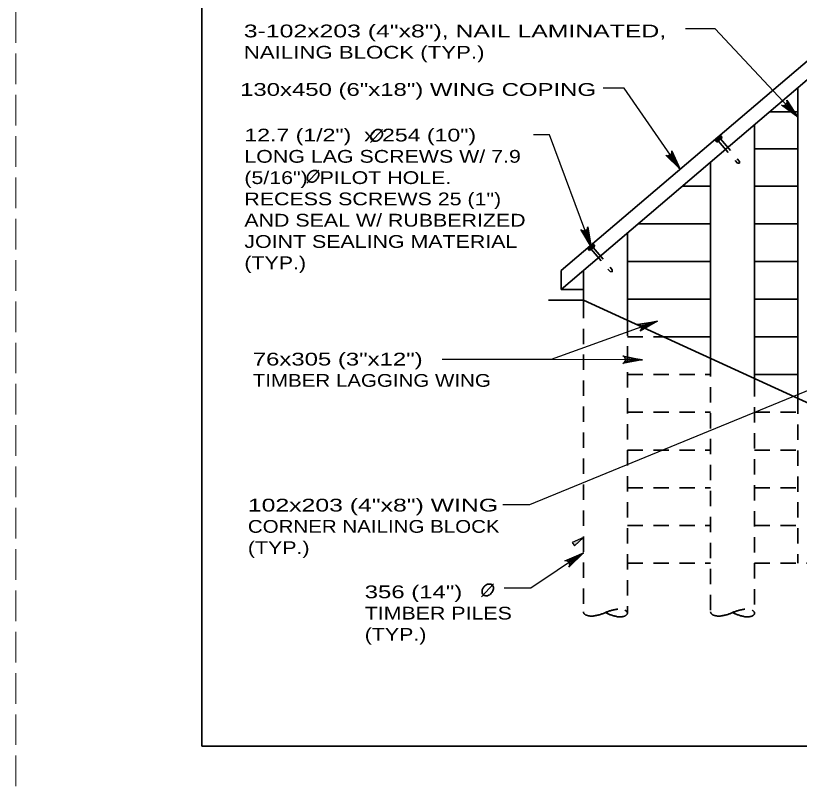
# Model space of a CAD drawing. Extents: x -6.4 to 73.1, y -66 to 0.
# Drawn here: x 0 to 7.36, y -43.62 to -36.39 of the extents above; entities that cross this region are included whole.
import ezdxf

# ---------------------------------------------------------------- set-up
doc = ezdxf.new("R2010")
doc.units = 0
doc.header["$LTSCALE"] = 0.048
doc.header["$PDMODE"] = 32
doc.header["$PDSIZE"] = 0.024
doc.linetypes.add('LONG_DASHED', pattern=[7.5, 6, -1.5])
doc.linetypes.add('MEDIUM_DASHED', pattern=[4.5, 3, -1.5])
for name, color, linetype, lineweight in [('1', 7, 'Continuous', 13), ('4', 7, 'Continuous', 25), ('5', 7, 'Continuous', 25), ('63', 7, 'LONG_DASHED', 13)]:
    doc.layers.add(name, color=color, linetype=linetype, lineweight=lineweight)

msp = doc.modelspace()

# ---------------------------------------------------------------- hatches: boundary and pattern name
at = {"layer": '5'}
for points in [[(7.34583, -37.3415), (7.2725, -37.24842), (7.25808, -37.26183)], [(5.22792, -41.33758), (5.249, -41.36892), (5.3325, -41.28992)], [(5.22792, -41.48342), (5.249, -41.51475), (5.3325, -41.43575)]]:
    msp.add_hatch(color=256, dxfattribs=at).paths.add_polyline_path(points)

# ---------------------------------------------------------------- linework, layer by layer
at = {"layer": '1', "lineweight": 35}
msp.add_lwpolyline([(1.75, -43.25), (33.25, -43.25), (33.25, -22.75), (1.75, -22.75)], close=True, dxfattribs=at)
at = {"layer": '4', "lineweight": 35}
for p, q in [((7.57942, -36.68917), (5.12433, -38.78225)), ((7.57942, -36.86633), (5.12433, -38.95942)), ((7.34583, -37.0655), (7.34583, -39.98392)), ((7.08275, -37.28975), (7.34583, -37.28975)), ((6.94125, -37.41042), (6.94125, -39.82258)), ((6.63567, -37.53292), (6.58458, -37.57642)), ((6.61208, -37.532), (6.5875, -37.553)), ((6.6105, -37.53833), (6.61842, -37.54767)), ((6.63567, -37.53292), (6.61633, -37.51025)), ((6.62625, -37.541), (6.61833, -37.53167)), ((6.58458, -37.57642), (6.56525, -37.55375)), ((6.59375, -37.56867), (6.58583, -37.55933)), ((6.59375, -37.56867), (6.62625, -37.541)), ((6.59425, -37.55217), (6.60217, -37.5615)), ((6.94125, -37.63908), (7.34583, -37.63908)), ((6.79825, -37.7745), (6.79917, -37.7565)), ((6.52783, -37.76283), (6.52783, -39.63292)), ((6.26333, -37.98833), (6.52783, -37.98833)), ((6.94125, -37.98833), (7.34583, -37.98833)), ((5.84775, -38.34267), (6.52783, -38.34267)), ((6.94125, -38.34267), (7.34583, -38.34267)), ((5.74592, -38.4295), (5.74592, -39.25017)), ((5.44033, -38.552), (5.38925, -38.5955)), ((5.41675, -38.55108), (5.39217, -38.57208)), ((5.39842, -38.58775), (5.43092, -38.56008)), ((5.39892, -38.57125), (5.40683, -38.58058)), ((5.41517, -38.55742), (5.42308, -38.56675)), ((5.44033, -38.552), (5.421, -38.52933)), ((5.43092, -38.56008), (5.423, -38.55075)), ((5.38925, -38.5955), (5.37, -38.57292)), ((5.39842, -38.58775), (5.3905, -38.57842)), ((5.74592, -38.697), (6.52783, -38.697)), ((6.94125, -38.697), (7.34583, -38.697)), ((5.12433, -38.78225), (5.12433, -38.95942)), ((5.3325, -38.78192), (5.3325, -39.08742)), ((5.12433, -38.95942), (5.3325, -38.95942)), ((5.00517, -39.06108), (5.3325, -39.06108)), ((5.33375, -39.06108), (7.8505, -40.21542)), ((5.74592, -39.05133), (6.52783, -39.05133)), ((6.94125, -39.05133), (7.34583, -39.05133)), ((6.085, -39.40567), (6.52783, -39.40567)), ((6.94125, -39.40567), (7.34583, -39.40567)), ((6.94125, -39.76), (7.34583, -39.76))]:
    msp.add_line(p, q, dxfattribs=at)
at = {"layer": '4', "linetype": 'MEDIUM_DASHED', "lineweight": 35}
for p, q in [((6.62, -37.54625), (6.79917, -37.7565)), ((5.42467, -38.56533), (5.60392, -38.77558)), ((5.3325, -39.08467), (5.3325, -41.99042)), ((5.74592, -39.25017), (5.74592, -42.0015)), ((5.74592, -39.29367), (5.74592, -39.36292)), ((5.74592, -39.40567), (6.085, -39.40567)), ((6.52783, -39.63292), (6.52783, -41.99042)), ((5.74592, -39.76), (6.52783, -39.76)), ((6.94125, -39.82258), (6.94125, -42.0015)), ((7.34583, -39.98392), (7.34583, -41.53167)), ((5.74592, -40.11433), (6.52783, -40.11433)), ((6.94125, -40.11433), (7.34583, -40.11433)), ((5.74592, -40.46867), (6.52783, -40.46867)), ((6.94125, -40.46867), (7.34583, -40.46867)), ((5.74592, -40.823), (6.52783, -40.823)), ((6.94125, -40.823), (7.34583, -40.823)), ((5.74592, -41.17733), (6.52783, -41.17733)), ((6.94125, -41.17733), (7.34583, -41.17733)), ((5.74592, -41.53167), (6.52783, -41.53167)), ((6.94125, -41.53167), (7.72817, -41.53167))]:
    msp.add_line(p, q, dxfattribs=at)
for points in [[(6.6, -37.56333), (6.77925, -37.7735), (6.79825, -37.7745)], [(5.40467, -38.58242), (5.58392, -38.79258), (5.603, -38.79358), (5.60392, -38.77558)]]:
    msp.add_lwpolyline(points, dxfattribs=at)
at = {"layer": '4', "lineweight": 35}
for centre, radius, start, end in [((6.61095, -37.5553), 0.01696, 91.4996, 169.39961), ((6.61546, -37.53624), 0.00539, 57.90141, 202.9978), ((6.59147, -37.5574), 0.00592, 128.62254, 199.16266), ((6.59147, -37.5574), 0.00592, 61.73655, 128.62254), ((5.39614, -38.57649), 0.00592, 61.73655, 128.62254), ((5.41562, -38.57439), 0.01696, 91.4996, 169.39961), ((5.42014, -38.55533), 0.00539, 57.90141, 202.9978), ((5.39614, -38.57649), 0.00592, 128.62254, 199.16266)]:
    msp.add_arc(centre, radius, start, end, dxfattribs=at)
at = {"layer": '4', "linetype": 'MEDIUM_DASHED', "lineweight": 35}
for centre, major_axis, start_param, end_param in [((5.40576, -41.99238), (-0.07323, 0.00196), 6.2831853, 8.1107827), ((5.3353, -41.88706), (-0.29233, 0.00784), 1.8903203, 2.3561945), ((5.74318, -42.10485), (0.29233, -0.00784), 1.8903203, 2.3561945), ((5.74872, -41.89815), (0.29233, -0.00784), 3.9269908, 4.392865), ((5.67272, -41.99954), (0.07323, -0.00196), 4.4555879, 8.1107827), ((6.60109, -41.99238), (-0.07323, 0.00196), 6.2831853, 8.1107827), ((6.53064, -41.88706), (-0.29233, 0.00784), 1.8903203, 2.3561945), ((6.93851, -42.10485), (0.29233, -0.00784), 1.8903203, 2.3561945), ((6.94405, -41.89815), (0.29233, -0.00784), 3.9269908, 4.392865), ((6.86806, -41.99954), (0.07323, -0.00196), 4.4555879, 8.1107827)]:
    msp.add_ellipse(centre, major_axis=major_axis, ratio=0.5, start_param=start_param, end_param=end_param, dxfattribs=at)
at = {"layer": '4'}
for p in [(6.589, -37.552), (6.58942, -37.55158), (6.58992, -37.55117), (6.59033, -37.55083), (6.5905, -37.55142), (6.59075, -37.55042), (6.59092, -37.55108), (6.59125, -37.55), (6.59142, -37.55067), (6.59158, -37.55133), (6.59167, -37.54967), (6.59183, -37.55033), (6.592, -37.55092), (6.59217, -37.54925), (6.59225, -37.54992), (6.5925, -37.55058), (6.59258, -37.54892), (6.59267, -37.55117), (6.59275, -37.5495), (6.59292, -37.55017), (6.593, -37.5485), (6.59308, -37.55083), (6.59317, -37.54917), (6.59325, -37.55142), (6.59333, -37.54983), (6.5935, -37.54808), (6.5935, -37.55042), (6.59367, -37.54875), (6.59367, -37.55108), (6.59383, -37.54942), (6.59383, -37.55175), (6.59392, -37.54775), (6.594, -37.55008), (6.59408, -37.54842), (6.59408, -37.55067), (6.59425, -37.549), (6.59425, -37.55133), (6.59433, -37.54733), (6.59442, -37.54967), (6.59458, -37.548), (6.59458, -37.55033), (6.59475, -37.54867), (6.59483, -37.547), (6.59483, -37.54933), (6.595, -37.54758), (6.59517, -37.54825), (6.59525, -37.54658), (6.59542, -37.54725), (6.59558, -37.54792), (6.59575, -37.54617), (6.59592, -37.54683), (6.59617, -37.54583), (6.59633, -37.5465), (6.59667, -37.54542), (6.59708, -37.54508), (6.5975, -37.54467), (6.598, -37.54433), (6.602, -37.54083), (6.6025, -37.54042), (6.60292, -37.54008), (6.60333, -37.53967), (6.60383, -37.53933), (6.60425, -37.53892), (6.60442, -37.53958), (6.60475, -37.5385), (6.60492, -37.53917), (6.60517, -37.53817), (6.60533, -37.53883), (6.60558, -37.53775), (6.60575, -37.53842), (6.60592, -37.53908), (6.60608, -37.53742), (6.60625, -37.53808), (6.60642, -37.53867), (6.6065, -37.537), (6.60667, -37.53767), (6.60683, -37.53833), (6.60692, -37.53667), (6.60717, -37.53725), (6.60733, -37.53792), (6.60742, -37.53625), (6.60742, -37.53858), (6.60758, -37.53692), (6.60775, -37.5375), (6.60783, -37.53583), (6.60792, -37.53817), (6.608, -37.5365), (6.60817, -37.53717), (6.60833, -37.53783), (6.60842, -37.53542), (6.6085, -37.53617), (6.6085, -37.53842), (6.60858, -37.53608), (6.60867, -37.53675), (6.60875, -37.53742), (6.60883, -37.535), (6.60892, -37.538), (6.609, -37.53567), (6.60917, -37.53633), (6.60925, -37.537), (6.60933, -37.53467), (6.60933, -37.537), (6.60942, -37.53533), (6.60942, -37.53767), (6.60958, -37.53592), (6.60958, -37.53833), (6.60975, -37.53425), (6.60975, -37.53658), (6.60992, -37.53492), (6.60992, -37.53725), (6.61, -37.53792), (6.61008, -37.53558), (6.61008, -37.53783), (6.61017, -37.53392), (6.61033, -37.5345), (6.61067, -37.5335), (6.61108, -37.53308), (5.39367, -38.57108), (5.39408, -38.57067), (5.39458, -38.57025), (5.395, -38.56992), (5.39517, -38.57058), (5.39542, -38.5695), (5.39558, -38.57017), (5.39592, -38.56917), (5.39608, -38.56975), (5.39625, -38.57042), (5.39633, -38.56875), (5.3965, -38.56942), (5.39667, -38.57), (5.39683, -38.56833), (5.397, -38.569), (5.39717, -38.56967), (5.39725, -38.568), (5.39733, -38.57025), (5.39742, -38.56858), (5.39758, -38.56925), (5.39767, -38.56758), (5.39775, -38.56992), (5.39792, -38.56825), (5.39792, -38.5705), (5.398, -38.56892), (5.39817, -38.56717), (5.39817, -38.5695), (5.39833, -38.56783), (5.39833, -38.57017), (5.3985, -38.5685), (5.3985, -38.57083), (5.39858, -38.56683), (5.39867, -38.56917), (5.39875, -38.5675), (5.39875, -38.56975), (5.39892, -38.56808), (5.39892, -38.57042), (5.39908, -38.56642), (5.39908, -38.56875), (5.39925, -38.56708), (5.39925, -38.56942), (5.39942, -38.56775), (5.3995, -38.56608), (5.3995, -38.56842), (5.39967, -38.56667), (5.39983, -38.56733), (5.39992, -38.56567), (5.40008, -38.56633), (5.40025, -38.567), (5.40042, -38.56525), (5.40058, -38.56592), (5.40083, -38.56492), (5.401, -38.56558), (5.40133, -38.5645), (5.40175, -38.56417), (5.40217, -38.56375), (5.40267, -38.56342), (5.40667, -38.55992), (5.40717, -38.55958), (5.40758, -38.55917), (5.408, -38.55875), (5.4085, -38.55842), (5.40892, -38.558), (5.40908, -38.55867), (5.40942, -38.55758), (5.40958, -38.55825), (5.40983, -38.55725), (5.41, -38.55792), (5.41025, -38.55683), (5.4105, -38.5575), (5.41058, -38.55817), (5.41075, -38.5565), (5.41092, -38.55717), (5.41108, -38.55775), (5.41117, -38.55608), (5.41133, -38.55675), (5.4115, -38.55742), (5.41167, -38.55575), (5.41183, -38.55633), (5.412, -38.557), (5.41208, -38.55533), (5.41208, -38.55767), (5.41225, -38.556), (5.41242, -38.55667), (5.4125, -38.55492), (5.41258, -38.55725), (5.41267, -38.55558), (5.41283, -38.55625), (5.413, -38.55692), (5.41308, -38.5545), (5.41317, -38.55525), (5.41317, -38.5575), (5.41325, -38.55517), (5.41333, -38.55583), (5.4135, -38.55408), (5.4135, -38.5565), (5.41358, -38.55717), (5.41367, -38.55475), (5.41383, -38.55542), (5.41392, -38.55617), (5.414, -38.55375), (5.414, -38.55608), (5.41408, -38.55442), (5.41408, -38.55675), (5.41425, -38.555), (5.41425, -38.55742), (5.41442, -38.55333), (5.41442, -38.55567), (5.41458, -38.554), (5.41458, -38.55633), (5.41467, -38.557), (5.41475, -38.55467), (5.41475, -38.55692), (5.41483, -38.553), (5.415, -38.55358), (5.41533, -38.55258), (5.41575, -38.55217)]:
    msp.add_point(p, dxfattribs=at)
at = {"layer": '5'}
for p, q in [((6.5705, -36.51008), (6.29308, -36.51008)), ((7.34583, -37.3415), (6.5705, -36.51008)), ((6.02833, -39.25717), (5.02883, -39.617)), ((5.02883, -39.617), (4.00658, -39.617)), ((5.88925, -39.621), (5.02883, -39.617)), ((7.61, -39.84025), (4.828, -40.98258)), ((4.828, -40.98258), (4.57492, -40.98258))]:
    msp.add_line(p, q, dxfattribs=at)
at = {"layer": '5', "lineweight": 35}
for p, q in [((3.33275, -37.57842), (3.44475, -37.45583)), ((2.73625, -37.96225), (2.84825, -37.83958)), ((4.377, -41.84858), (4.489, -41.72592))]:
    msp.add_line(p, q, dxfattribs=at)
at = {"layer": '5'}
for points in [[(6.24075, -37.83042), (5.71417, -37.07033), (5.51975, -37.07033)], [(7.34583, -37.3415), (7.19317, -37.229), (7.21025, -37.23275), (7.22442, -37.22958), (7.235, -37.22267), (7.24267, -37.21258), (7.24675, -37.19858), (7.24425, -37.18133), (7.34583, -37.3415), (7.24675, -37.19858), (7.24267, -37.21258), (7.34583, -37.3415), (7.235, -37.22267), (7.22442, -37.22958), (7.34583, -37.3415), (7.21025, -37.23275)], [(5.40692, -38.5595), (5.0155, -37.50758), (4.86442, -37.50758)], [(6.24075, -37.83042), (6.10592, -37.69708), (6.11408, -37.70017), (6.12225, -37.70325), (6.1295, -37.70275), (6.13675, -37.70225), (6.1425, -37.69958), (6.14825, -37.69683), (6.15275, -37.69242), (6.15725, -37.688), (6.16033, -37.68142), (6.16333, -37.67475), (6.16333, -37.66608), (6.16333, -37.65733), (6.24075, -37.83042), (6.16333, -37.66608), (6.16333, -37.67475), (6.24075, -37.83042), (6.16033, -37.68142), (6.15725, -37.688), (6.24075, -37.83042), (6.15275, -37.69242), (6.14825, -37.69683), (6.24075, -37.83042), (6.1425, -37.69958), (6.13675, -37.70225), (6.24075, -37.83042), (6.1295, -37.70275), (6.12225, -37.70325), (6.24075, -37.83042), (6.11408, -37.70017)], [(5.40692, -38.5595), (5.30908, -38.397), (5.31625, -38.402), (5.32342, -38.407), (5.33058, -38.40825), (5.33775, -38.40958), (5.344, -38.40842), (5.35025, -38.40725), (5.35567, -38.40408), (5.36117, -38.40083), (5.36575, -38.39525), (5.37033, -38.38958), (5.3725, -38.38108), (5.37467, -38.37267), (5.40692, -38.5595), (5.3725, -38.38108), (5.37033, -38.38958), (5.40692, -38.5595), (5.36575, -38.39525), (5.36117, -38.40083), (5.40692, -38.5595), (5.35567, -38.40408), (5.35025, -38.40725), (5.40692, -38.5595), (5.344, -38.40842), (5.33775, -38.40958), (5.40692, -38.5595), (5.33058, -38.40825), (5.32342, -38.407), (5.40692, -38.5595), (5.31625, -38.402)], [(6.02833, -39.25717), (5.86475, -39.35317), (5.87492, -39.339), (5.87767, -39.32467), (5.87542, -39.31225), (5.86917, -39.30117), (5.858, -39.29192), (5.84108, -39.28742), (6.02833, -39.25717), (5.858, -39.29192), (5.86917, -39.30117), (6.02833, -39.25717), (5.87542, -39.31225), (5.87767, -39.32467), (6.02833, -39.25717), (5.87492, -39.339)], [(5.88925, -39.621), (5.70267, -39.65508), (5.71708, -39.64517), (5.72458, -39.63275), (5.72675, -39.62025), (5.72467, -39.60775), (5.71733, -39.59517), (5.703, -39.58517), (5.88925, -39.621), (5.71733, -39.59517), (5.72467, -39.60775), (5.88925, -39.621), (5.72675, -39.62025), (5.72458, -39.63275), (5.88925, -39.621), (5.71708, -39.64517)], [(5.3325, -41.43575), (4.8405, -41.76683), (4.58908, -41.76683)], [(5.3325, -41.43575), (5.19733, -41.56883), (5.20375, -41.55258), (5.20292, -41.538), (5.19767, -41.5265), (5.18892, -41.51733), (5.17583, -41.51108), (5.15833, -41.51083), (5.3325, -41.43575), (5.17583, -41.51108), (5.18892, -41.51733), (5.3325, -41.43575), (5.19767, -41.5265), (5.20292, -41.538), (5.3325, -41.43575), (5.20375, -41.55258)]]:
    msp.add_lwpolyline(points, dxfattribs=at)
for points in [[(7.34583, -37.3415), (7.2725, -37.24842), (7.25808, -37.26183)], [(5.22792, -41.33758), (5.249, -41.36892), (5.3325, -41.28992)], [(5.22792, -41.48342), (5.249, -41.51475), (5.3325, -41.43575)]]:
    msp.add_lwpolyline(points, close=True, dxfattribs=at)
at = {"layer": '5', "lineweight": 35}
for points in [[(3.43308, -37.46792), (3.42433, -37.46108), (3.41558, -37.45867), (3.40458, -37.45767), (3.39833, -37.45767), (3.38758, -37.46017), (3.37775, -37.46467), (3.37083, -37.46858), (3.35758, -37.47917), (3.34725, -37.49267), (3.341, -37.50533), (3.33733, -37.51692), (3.33625, -37.52767), (3.33733, -37.53692), (3.34183, -37.55008), (3.34658, -37.55692), (3.35625, -37.56417), (3.37075, -37.56767), (3.38725, -37.56717), (3.40808, -37.55767), (3.42333, -37.54458), (3.43483, -37.52867), (3.44233, -37.51208), (3.44483, -37.49367), (3.44158, -37.48183), (3.43358, -37.46792)], [(2.83658, -37.85175), (2.82783, -37.84483), (2.81908, -37.8425), (2.80808, -37.8415), (2.80183, -37.8415), (2.79108, -37.844), (2.78125, -37.8485), (2.77433, -37.85233), (2.76108, -37.863), (2.75075, -37.8765), (2.7445, -37.88908), (2.74083, -37.90075), (2.73975, -37.9115), (2.74083, -37.92075), (2.74533, -37.93383), (2.75008, -37.94075), (2.75975, -37.948), (2.77425, -37.9515), (2.79075, -37.951), (2.81158, -37.9415), (2.82683, -37.92833), (2.83833, -37.9125), (2.84583, -37.89583), (2.84833, -37.8775), (2.84508, -37.86558), (2.83708, -37.85175)], [(4.47733, -41.73808), (4.46858, -41.73117), (4.45983, -41.72883), (4.44883, -41.72783), (4.44258, -41.72783), (4.43183, -41.73033), (4.422, -41.73483), (4.41508, -41.73867), (4.40183, -41.74933), (4.3915, -41.76283), (4.38525, -41.77542), (4.38158, -41.78708), (4.3805, -41.79783), (4.38158, -41.80708), (4.38608, -41.82017), (4.39083, -41.82708), (4.4005, -41.83433), (4.415, -41.83783), (4.4315, -41.83733), (4.45233, -41.82783), (4.46758, -41.81467), (4.47908, -41.79883), (4.48658, -41.78217), (4.48908, -41.76383), (4.48583, -41.75192), (4.47783, -41.73808)]]:
    msp.add_spline(points, degree=3, dxfattribs=at)
at = {"layer": '63'}
msp.add_lwpolyline([(0, -44), (34, -44), (34, -22), (0, -22)], close=True, dxfattribs=at)

# ---------------------------------------------------------------- texts
at = {"layer": '5'}
for s, width, p in [('3-102x203 (4"x8"), NAIL LAMINATED,', 1.45, (2.14292, -36.5915)), ('NAILING BLOCK (TYP.)', 1.3, (2.14292, -36.7915)), ('130x450 (6"x18") WING COPING', 1.4, (2.10808, -37.14125)), ('12.7 (1/2")  x 254 (10")', 1.35, (2.14817, -37.56942)), ('LONG LAG SCREWS W/ 7.9', 1.25, (2.14817, -37.76942)), ('(5/16")  PILOT HOLE.', 1.25, (2.14817, -37.96942)), ('RECESS SCREWS 25 (1")', 1.25, (2.14817, -38.16942)), ('AND SEAL W/ RUBBERIZED', 1.25, (2.14817, -38.36942)), ('JOINT SEALING MATERIAL', 1.25, (2.14817, -38.56942)), ('(TYP.)', 1.25, (2.14817, -38.76942)), ('76x305 (3"x12")', 1.4, (2.22717, -39.67458)), ('TIMBER LAGGING WING', 1.2, (2.22717, -39.87458)), ('102x203 (4"x8") WING', 1.45, (2.181, -41.04633)), ('CORNER NAILING BLOCK', 1.2, (2.181, -41.24633)), ('(TYP.)', 1.25, (2.181, -41.44633)), ('356 (14") ', 1.4, (3.2785, -41.86117)), ('TIMBER PILES', 1.25, (3.2785, -42.06117)), ('(TYP.)', 1.25, (3.2785, -42.26117))]:
    msp.add_text(s, height=0.12, dxfattribs=dict(at, width=width)).set_placement(p)

doc.saveas('drawing.dxf')
